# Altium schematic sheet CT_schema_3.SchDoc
size 282 x 169 mm
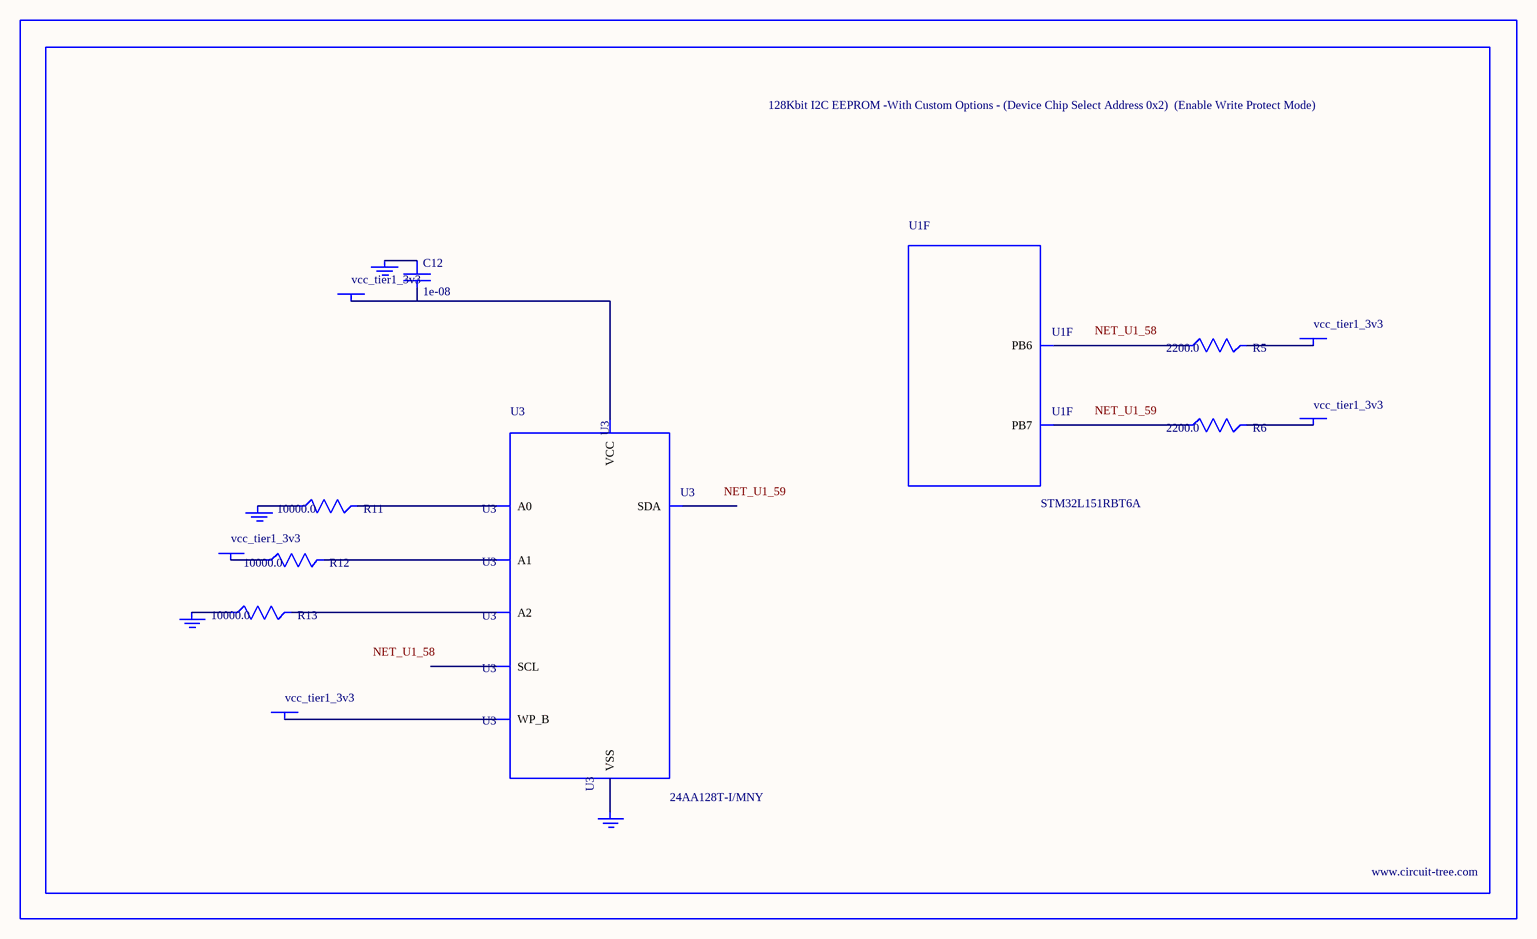
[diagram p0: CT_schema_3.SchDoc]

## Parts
BORDER2  (no value)
C12  1e-08  [C0402]
GND_INSTANCE_2_0  (no value)
GND_INSTANCE_2_1  (no value)
GND_INSTANCE_2_2  (no value)
GND_INSTANCE_2_3  (no value)
POWER_INSTANCE_2_0  vcc_tier1_3v3
POWER_INSTANCE_2_1  vcc_tier1_3v3
POWER_INSTANCE_2_2  vcc_tier1_3v3
POWER_INSTANCE_2_3  vcc_tier1_3v3
POWER_INSTANCE_2_4  vcc_tier1_3v3
R5  2200.0  [R0603]
R6  2200.0  [R0603]
R11  10000.0  [R0603]
R12  10000.0  [R0603]
R13  10000.0  [R0603]
U1  STM32L151RBT6A  [LQFP64]  (part F of 7)
U3  24AA128T-I/MNY  [TDFN-8/6MM]

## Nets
NetC12_1: C12.1 GND_INSTANCE_2_2.0(GND)
NetC12_2: C12.2 POWER_INSTANCE_2_2.0(PWR) U3.8(VCC)
NetGND_INSTANCE_2_0_0: GND_INSTANCE_2_0.0(GND) R11.1
NetGND_INSTANCE_2_1_0: GND_INSTANCE_2_1.0(GND) R13.1
NetGND_INSTANCE_2_3_0: GND_INSTANCE_2_3.0(GND) U3.4(VSS)
NetPOWER_INSTANCE_2_0_0: POWER_INSTANCE_2_0.0(PWR) R12.1
NetPOWER_INSTANCE_2_1_0: POWER_INSTANCE_2_1.0(PWR) U3.7(WP_B)
NetPOWER_INSTANCE_2_3_0: POWER_INSTANCE_2_3.0(PWR) R5.2
NetPOWER_INSTANCE_2_4_0: POWER_INSTANCE_2_4.0(PWR) R6.2
NetR5_1: R5.1 U1.58(PB6)
NetR6_1: R6.1 U1.59(PB7)
NetR11_2: R11.2 U3.1(A0)
NetR12_2: R12.2 U3.2(A1)
NetR13_2: R13.2 U3.3(A2)

Not connected (* = marked no-connect by the designer): U3 5(SDA) 6(SCL)

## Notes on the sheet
- Labels drawn without touching a wire or pin: NET_U1_58, NET_U1_59

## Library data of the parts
BORDER2 = BORDER_PAGE2
C12 = C0402C103K3RAC
GND_INSTANCE_2_0-GND_INSTANCE_2_3 = GND
POWER_INSTANCE_2_0-POWER_INSTANCE_2_4 = PWR
R5 R6 = RC0603JR-072K2L
R11-R13 = RC0603JR-0710KL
